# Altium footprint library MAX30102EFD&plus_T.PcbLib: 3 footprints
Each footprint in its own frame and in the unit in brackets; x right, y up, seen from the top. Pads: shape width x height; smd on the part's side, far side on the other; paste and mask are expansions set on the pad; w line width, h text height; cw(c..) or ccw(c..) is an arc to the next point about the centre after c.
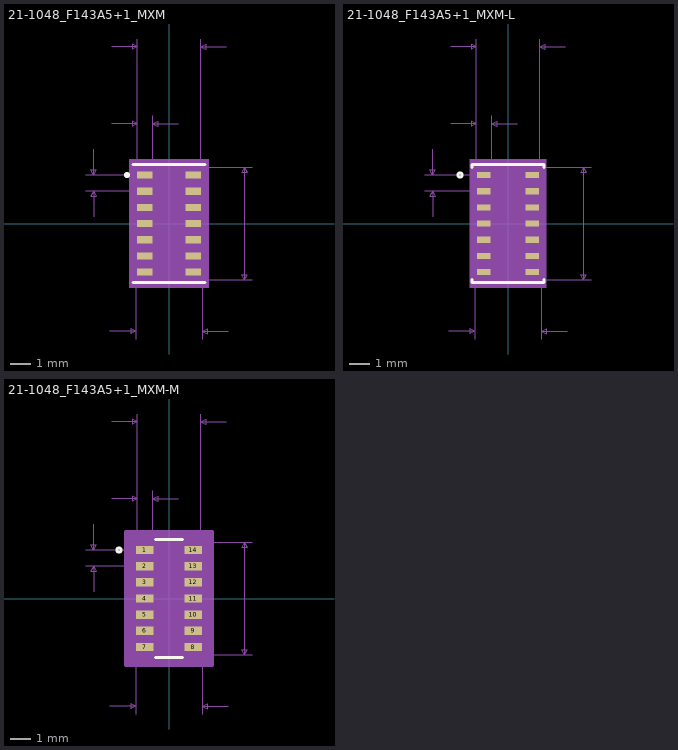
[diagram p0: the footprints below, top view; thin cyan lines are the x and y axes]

## 21-1048_F143A5+1_MXM [mil]
pads (14):
  rect 30x14 smd paste+0 mask+0: 1(-47,94.49) 2(-47,62.99) 3(-47,31.5) 4(-47,0) 5(-47,-31.5) 6(-47,-62.99) 7(-47,-94.49) 8(47,-94.49) 9(47,-62.99) 10(47,-31.5) 11(47,0) 12(47,31.5) 13(47,62.99) 14(47,94.49)
Top Overlay:
  circle w6: c-81.75,94.49 r3
  lines w6: -70,-115 70,-115 ; -70,115 70,115
Mechanical 5:
  region: 77,-125 -77,-125 -77,125 77,125
Mechanical 7:
  lines w1: -162,62.99 -47,62.99 ; -162,94.49 -47,94.49 ; -147,12.99 -147,62.99 ; -147,144.49 -147,94.49 ; -115,-210 -65,-210 ; -112,194.49 -62,194.49 ; -112,344.49 -62,344.49 ; -65,-225 -65,-110 ; -62,209.49 -62,94.49 -62,359.49 ; -32,94.49 -32,209.49 ; 18,194.49 -32,194.49 ; 62,94.49 62,359.49 ; 65,-225 65,-110 162,-110 ; 65,110 162,110 ; 112,344.49 62,344.49 ; 115,-210 65,-210 ; -147,62.99 -152,52.99 -142,52.99 -147,62.99 ; -147,94.49 -152,104.49 -142,104.49 -147,94.49 ; -65,-210 -75,-205 -75,-215 -65,-210 ; -62,194.49 -72,199.49 -72,189.49 -62,194.49 ; -62,344.49 -72,349.49 -72,339.49 -62,344.49 ; -32,194.49 -22,199.49 -22,189.49 -32,194.49 ; 62,344.49 72,349.49 72,339.49 62,344.49 ; 65,-210 75,-205 75,-215 65,-210 ; 147,-110 147,110 ; 147,-110 142,-100 152,-100 147,-110 ; 147,110 142,100 152,100 147,110
  text "Default Padstyle: RX30Y14D0T" at -350,-480 h50
  text "Alt 1 Padstyle: OX60Y90D30P" at -337.5,-660 h50
  text "Alt 2 Padstyle: OX90Y60D30P" at -337.5,-720 h50
  text "0.124in/3.15mm" at -87.5,364.49 h25
  text "0.03in/0.762mm" at -134.5,214.49 h25
  text "0.031in/0.8mm" at -329.5,66.24 h25
  text "0.22in/5.588mm" at 167,-12.5 h25
  text "0.13in/3.302mm" at -87.5,-255 h25
Mechanical 13:
  circle w6: c-32,94.49 r3
  lines w0: -12,110 ccw(c0,110) 12,110
  lines w1: -65,-110 65,-110 65,110 -65,110 -65,-110
Mechanical 15:
  region: -75,-111.49 -75,111.49 -75,120 75,120 75,111.49 75,-111.49 75,-120 -75,-120
  lines w6: -75,-111.49 -75,111.49 ; -75,-111.49 -75,-111.49 ; -75,-111.49 -75,-120 75,-120 75,-111.49 ; -75,111.49 -75,111.49 ; -75,111.49 -75,120 75,120 75,111.49 ; 75,-111.49 75,111.49 ; 75,-111.49 75,-111.49 ; 75,111.49 75,111.49
3D body: height 10, standoff 0, extent 0,0 10,10

## 21-1048_F143A5+1_MXM-L [mil]
pads (14):
  rect 26x12 smd paste+0 mask+0: 1(-47,94.49) 2(-47,62.99) 3(-47,31.5) 4(-47,0) 5(-47,-31.5) 6(-47,-62.99) 7(-47,-94.49) 8(47,-94.49) 9(47,-62.99) 10(47,-31.5) 11(47,0) 12(47,31.5) 13(47,62.99) 14(47,94.49)
Top Overlay:
  circle w6: c-93.5,94.49 r4
  lines w6: -70,-108.95 -70,-115 70,-115 70,-108.95 ; -70,108.95 -70,115 70,115 70,108.95
Mechanical 5:
  region: 75,-125 -75,-125 -75,125 75,125
Mechanical 7:
  lines w1: -162,62.99 -47,62.99 ; -162,94.49 -47,94.49 ; -147,12.99 -147,62.99 ; -147,144.49 -147,94.49 ; -115,-210 -65,-210 ; -112,194.49 -62,194.49 ; -112,344.49 -62,344.49 ; -65,-225 -65,-110 ; -62,209.49 -62,94.49 -62,359.49 ; -32,94.49 -32,209.49 ; 18,194.49 -32,194.49 ; 62,94.49 62,359.49 ; 65,-225 65,-110 162,-110 ; 65,110 162,110 ; 112,344.49 62,344.49 ; 115,-210 65,-210 ; -147,62.99 -152,52.99 -142,52.99 -147,62.99 ; -147,94.49 -152,104.49 -142,104.49 -147,94.49 ; -65,-210 -75,-205 -75,-215 -65,-210 ; -62,194.49 -72,199.49 -72,189.49 -62,194.49 ; -62,344.49 -72,349.49 -72,339.49 -62,344.49 ; -32,194.49 -22,199.49 -22,189.49 -32,194.49 ; 62,344.49 72,349.49 72,339.49 62,344.49 ; 65,-210 75,-205 75,-215 65,-210 ; 147,-110 147,110 ; 147,-110 142,-100 152,-100 147,-110 ; 147,110 142,100 152,100 147,110
  text "Default Padstyle: RX26Y12D0T" at -350,-480 h50
  text "Alt 1 Padstyle: OX60Y90D30P" at -337.5,-660 h50
  text "Alt 2 Padstyle: OX90Y60D30P" at -337.5,-720 h50
  text "0.124in/3.15mm" at -87.5,364.49 h25
  text "0.03in/0.762mm" at -134.5,214.49 h25
  text "0.031in/0.8mm" at -329.5,66.24 h25
  text "0.22in/5.588mm" at 167,-12.5 h25
  text "0.13in/3.302mm" at -87.5,-255 h25
Mechanical 13:
  circle w0: c-34,94.49 r3
  lines w0: -12,110 ccw(c0,110) 12,110
  lines w1: -65,-110 65,-110 65,110 -65,110 -65,-110
Mechanical 15:
  region: -69,-104.49 -69,104.49 -69,114 69,114 69,104.49 69,-104.49 69,-114 -69,-114
  lines w6: -69,-104.49 -69,104.49 ; -69,-104.49 -69,-104.49 ; -69,-104.49 -69,-114 69,-114 69,-104.49 ; -69,104.49 -69,104.49 ; -69,104.49 -69,114 69,114 69,104.49 ; 69,-104.49 69,104.49 ; 69,-104.49 69,-104.49 ; 69,104.49 69,104.49
3D body: height 10, standoff 0, extent 0,0 10,10

## 21-1048_F143A5+1_MXM-M [mil]
pads (14):
  rect 34x16 smd paste+0 mask+0: 1(-47,94.49) 2(-47,62.99) 3(-47,31.5) 4(-47,0) 5(-47,-31.5) 6(-47,-62.99) 7(-47,-94.49) 8(47,-94.49) 9(47,-62.99) 10(47,-31.5) 11(47,0) 12(47,31.5) 13(47,62.99) 14(47,94.49)
Top Overlay:
  circle w6: c-97.5,94.49 r4
  lines w6: -26.12,-115 26.12,-115 ; -26.12,115 26.12,115
Mechanical 5:
  region: 79,-125 -79,-125 -79,125 79,125
Mechanical 7:
  lines w1: -162,62.99 -47,62.99 ; -162,94.49 -47,94.49 ; -147,12.99 -147,62.99 ; -147,144.49 -147,94.49 ; -115,-210 -65,-210 ; -112,194.49 -62,194.49 ; -112,344.49 -62,344.49 ; -65,-225 -65,-110 ; -62,209.49 -62,94.49 -62,359.49 ; -32,94.49 -32,209.49 ; 18,194.49 -32,194.49 ; 62,94.49 62,359.49 ; 65,-225 65,-110 162,-110 ; 65,110 162,110 ; 112,344.49 62,344.49 ; 115,-210 65,-210 ; -147,62.99 -152,52.99 -142,52.99 -147,62.99 ; -147,94.49 -152,104.49 -142,104.49 -147,94.49 ; -65,-210 -75,-205 -75,-215 -65,-210 ; -62,194.49 -72,199.49 -72,189.49 -62,194.49 ; -62,344.49 -72,349.49 -72,339.49 -62,344.49 ; -32,194.49 -22,199.49 -22,189.49 -32,194.49 ; 62,344.49 72,349.49 72,339.49 62,344.49 ; 65,-210 75,-205 75,-215 65,-210 ; 147,-110 147,110 ; 147,-110 142,-100 152,-100 147,-110 ; 147,110 142,100 152,100 147,110
  text "Default Padstyle: RX34Y16D0T" at -350,-480 h50
  text "Alt 1 Padstyle: OX60Y90D30P" at -337.5,-660 h50
  text "Alt 2 Padstyle: OX90Y60D30P" at -337.5,-720 h50
  text "0.124in/3.15mm" at -87.5,364.49 h25
  text "0.03in/0.762mm" at -134.5,214.49 h25
  text "0.031in/0.8mm" at -329.5,66.24 h25
  text "0.22in/5.588mm" at 167,-12.5 h25
  text "0.13in/3.302mm" at -87.5,-255 h25
Mechanical 13:
  circle w0: c-30,94.49 r3
  lines w0: -12,110 ccw(c0,110) 12,110
  lines w1: -65,-110 65,-110 65,110 -65,110 -65,-110
Mechanical 15:
  region: -85,-122.49 -85,122.49 -85,130 85,130 85,122.49 85,-122.49 85,-130 -85,-130
  lines w6: -85,-122.49 -85,122.49 ; -85,-122.49 -85,-122.49 ; -85,-122.49 -85,-130 85,-130 85,-122.49 ; -85,122.49 -85,122.49 ; -85,122.49 -85,130 85,130 85,122.49 ; 85,-122.49 85,122.49 ; 85,-122.49 85,-122.49 ; 85,122.49 85,122.49
3D body: height 10, standoff 0, extent 0,0 10,10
